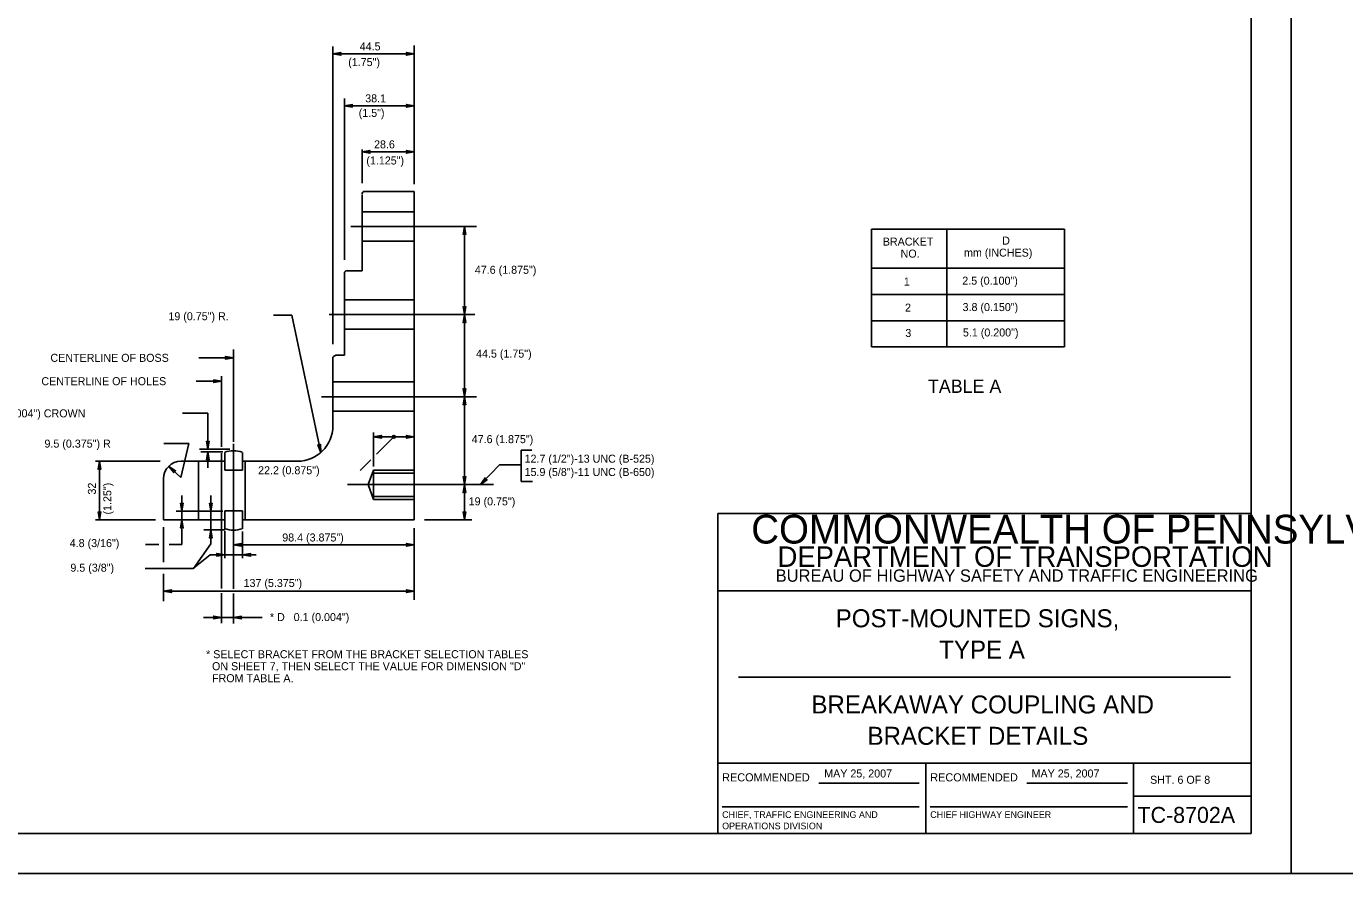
# Model space of a CAD drawing. Extents: x 637580 to 641008, y 294594 to 295782.
# Drawn here: x 638788.2 to 639282.3, y 294593.6 to 294911.2 of the extents above; entities that cross this region are included whole.
import ezdxf

# ---------------------------------------------------------------- set-up
doc = ezdxf.new("R2010")
doc.units = 0
for name, color, linetype in [('1', 7, 'Continuous'), ('2', 7, 'Continuous'), ('3', 7, 'Continuous'), ('PLT-BNDY', 7, 'Continuous')]:
    doc.layers.add(name, color=color, linetype=linetype)

# ---------------------------------------------------------------- blocks, each defined once
blk = doc.blocks.new('RARROW')
at = {"layer": '3'}
blk.add_lwpolyline([(-2.2695, 0.285), (-2.184875, 0.12075), (0, 0), (-2.2695, 0.285), (-2.38575, 0.384625), (0, 0), (-2.183125, -0.108), (-2.262875, -0.2705), (0, 0), (-2.38575, -0.379125), (-2.262875, -0.2705)], dxfattribs=at)

msp = doc.modelspace()

# ---------------------------------------------------------------- linework, layer by layer
at = {"layer": '1'}
for p, q in [((639247.31, 294608.63), (639247.31, 295172.63)), ((639047.31, 294608.63), (639047.31, 294728.63)), ((639047.31, 294728.63), (639247.31, 294728.63)), ((639247.31, 294699.63), (639047.31, 294699.63)), ((639055.06, 294667.31), (639239.56, 294667.31)), ((639047.31, 294635), (639247.31, 294635)), ((639125.31, 294635), (639125.31, 294608.63)), ((639203.19, 294608.63), (639203.19, 294635)), ((639085.24, 294627.57), (639122.87, 294627.57)), ((639163.24, 294627.57), (639200.87, 294627.57)), ((639203.19, 294622.63), (639247.31, 294622.63)), ((639048.99, 294618.68), (639122.87, 294618.68)), ((639126.99, 294618.68), (639200.87, 294618.68)), ((639247.31, 294608.63), (638461.31, 294608.63)), ((638461.31, 294608.63), (639047.31, 294608.63))]:
    msp.add_line(p, q, dxfattribs=at)
at = {"layer": '2'}
for p, q in [((638903.08, 294792.1), (638903.08, 294903.63)), ((638933.59, 294852.04), (638933.59, 294904.07)), ((638933.59, 294900.92), (638903.08, 294900.92)), ((638907.4, 294823.69), (638907.4, 294884.24)), ((638933.59, 294881.47), (638907.4, 294881.47)), ((638914.02, 294852.45), (638914.02, 294865.12)), ((638933.59, 294864.18), (638914.02, 294864.18)), ((638933.59, 294849.34), (638914.96, 294849.34)), ((638933.59, 294836.25), (638933.59, 294849.34)), ((638914.02, 294848.13), (638914.02, 294819.64)), ((638933.59, 294841.65), (638914.02, 294841.65)), ((638909.83, 294836.25), (638933.59, 294836.25)), ((638933.59, 294803.17), (638933.59, 294836.25)), ((638956.95, 294836.25), (638933.59, 294836.25)), ((638952.36, 294803.17), (638952.36, 294836.25)), ((639104.98, 294835.25), (639104.98, 294791.12)), ((639177.33, 294835.25), (639104.98, 294835.25)), ((639133.23, 294835.25), (639133.23, 294791.12)), ((639177.33, 294835.25), (639177.33, 294791.12)), ((638933.59, 294830.71), (638914.02, 294830.71)), ((638914.02, 294819.64), (638908.48, 294819.64)), ((639177.33, 294820.62), (639104.98, 294820.62)), ((638907.4, 294818.7), (638907.4, 294787.92)), ((639177.33, 294810.75), (639104.98, 294810.75)), ((638933.59, 294808.71), (638907.4, 294808.71)), ((638887.67, 294802.93), (638880.76, 294802.93)), ((638887.67, 294802.93), (638898.59, 294751.54)), ((638901.73, 294803.17), (638933.59, 294803.17)), ((638933.59, 294772.39), (638933.59, 294803.17)), ((638956.27, 294803.17), (638933.59, 294803.17)), ((638952.36, 294772.39), (638952.36, 294803.17)), ((639177.33, 294800.87), (639104.98, 294800.87)), ((638933.59, 294797.77), (638907.4, 294797.77)), ((638865.82, 294755.52), (638865.82, 294790.08)), ((639177.33, 294791.12), (639104.98, 294791.12)), ((638865.82, 294786.97), (638852.79, 294786.97)), ((638903.08, 294786.84), (638903.08, 294761.46)), ((638907.4, 294787.92), (638904.03, 294787.92)), ((638861.37, 294753.63), (638861.37, 294780.09)), ((638861.37, 294778.2), (638851.86, 294778.2)), ((638933.59, 294777.93), (638903.08, 294777.93)), ((638898.76, 294772.39), (638933.59, 294772.39)), ((638933.59, 294739.45), (638933.59, 294772.39)), ((638956.95, 294772.39), (638933.59, 294772.39)), ((638952.36, 294739.45), (638952.36, 294772.39)), ((638856.24, 294766.18), (638846.75, 294766.18)), ((638856.24, 294752.68), (638856.24, 294766.18)), ((638933.59, 294766.99), (638903.08, 294766.99)), ((638918.34, 294746.2), (638918.34, 294759.02)), ((638933.59, 294757.4), (638918.34, 294757.4)), ((638925.96, 294757.4), (638919.38, 294750.81)), ((638849.08, 294754.84), (638839.71, 294754.84)), ((638849.08, 294754.84), (638846.11, 294742.15)), ((638864.47, 294752.68), (638853.13, 294752.68)), ((638861.77, 294751.74), (638853.54, 294751.74)), ((638856.24, 294745.8), (638856.24, 294751.74)), ((638861.37, 294721.09), (638861.37, 294751.2)), ((638862.58, 294751.47), (638862.58, 294744.85)), ((638865.82, 294742.83), (638865.82, 294754.71)), ((638869.2, 294744.85), (638869.2, 294751.47)), ((638977.71, 294752.39), (638973.69, 294752.39)), ((638973.69, 294740.63), (638973.69, 294752.39)), ((638838.28, 294748.23), (638814.12, 294748.23)), ((638815.6, 294726.22), (638815.6, 294748.23)), ((638846.11, 294742.15), (638841.54, 294746.3)), ((638846.11, 294748.23), (638862.58, 294748.23)), ((638852.73, 294748.23), (638852.73, 294726.22)), ((638869.2, 294748.23), (638889.85, 294748.23)), ((638870.14, 294726.22), (638870.14, 294748.23)), ((638917.34, 294748.77), (638913.36, 294744.79)), ((638965.59, 294746.88), (638958.43, 294739.45)), ((638973.69, 294746.88), (638965.59, 294746.88)), ((638839.63, 294726.22), (638839.63, 294741.48)), ((638862.58, 294744.85), (638869.2, 294744.85)), ((638865.82, 294744.85), (638865.82, 294744.85)), ((638865.82, 294731.62), (638865.82, 294742.83)), ((638918.34, 294744.85), (638916.31, 294739.45)), ((638933.59, 294744.85), (638918.34, 294744.85)), ((638918.34, 294733.92), (638918.34, 294744.85)), ((638933.59, 294743.77), (638918.34, 294743.77)), ((638977.93, 294740.63), (638973.69, 294740.63)), ((638846.52, 294716.98), (638846.52, 294735.4)), ((638857.32, 294717.31), (638857.32, 294735.4)), ((638861.37, 294735.67), (638861.37, 294735.67)), ((638861.37, 294735.67), (638861.37, 294735.67)), ((638908.62, 294739.45), (638933.59, 294739.45)), ((638916.31, 294739.45), (638918.34, 294733.92)), ((638933.59, 294726.22), (638933.59, 294739.45)), ((638963.29, 294739.45), (638933.59, 294739.45)), ((638952.36, 294726.22), (638952.36, 294739.45)), ((638865.82, 294720.69), (638865.82, 294731.62)), ((638933.59, 294735), (638918.34, 294735)), ((638933.59, 294733.92), (638918.34, 294733.92)), ((638836.53, 294726.22), (638814.12, 294726.22)), ((638839.63, 294726.22), (638839.63, 294726.22)), ((638839.63, 294726.22), (638862.58, 294726.22)), ((638861.77, 294729.46), (638844.36, 294729.46)), ((638862.58, 294729.6), (638869.2, 294729.6)), ((638862.58, 294722.85), (638862.58, 294729.6)), ((638865.82, 294729.6), (638865.82, 294729.6)), ((638869.2, 294729.6), (638869.2, 294722.85)), ((638869.2, 294726.22), (638933.59, 294726.22)), ((638955.19, 294726.22), (638937.37, 294726.22)), ((638839.63, 294710.43), (638839.63, 294723.52)), ((638862.72, 294722.44), (638854.75, 294722.44)), ((638861.37, 294700.45), (638861.37, 294721.09)), ((638862.58, 294711.91), (638862.58, 294722.04)), ((638865.82, 294700.33), (638865.82, 294720.69)), ((638869.2, 294711.91), (638869.2, 294721.9)), ((638933.59, 294696.25), (638933.59, 294723.12)), ((638837.79, 294716.98), (638832.85, 294716.98)), ((638846.52, 294716.98), (638841.72, 294716.98)), ((638857.32, 294717.31), (638850.84, 294708)), ((638933.59, 294716.91), (638865.82, 294716.91)), ((638857.05, 294713.13), (638850.84, 294708.13)), ((638874.33, 294713.13), (638857.05, 294713.13)), ((638850.84, 294708), (638832.7, 294708)), ((638839.63, 294695.71), (638839.63, 294705.97)), ((638933.59, 294699.49), (638839.63, 294699.49)), ((638861.37, 294687.48), (638861.37, 294698.71)), ((638865.82, 294687.34), (638865.82, 294698.65)), ((638876.57, 294689.64), (638854.62, 294689.64))]:
    msp.add_line(p, q, dxfattribs=at)
msp.add_circle((638925.96, 294757.4), 0.5, dxfattribs=at)
msp.add_arc((638889.85, 294761.46), 13.23, 270, 0, dxfattribs=at)
for centre, major_axis, ratio, start_param, end_param in [((638915.09, 294848.27), (0, -1.1), 0.996388, 3.141593, 4.712389), ((638908.5, 294818.61), (0, -1.1), 0.996388, 3.141593, 4.712389), ((638904.12, 294786.75), (0, -1.1), 0.996388, 3.141593, 4.712389), ((638865.84, 294741.81), (0, -10.3), 0.996388, 2.814747, 3.468439), ((638846.14, 294741.63), (0, -6.6), 0.985297, 3.141593, 4.712389), ((638865.84, 294732.68), (0, -10.3), 0.996388, 5.956339, 6.610031)]:
    msp.add_ellipse(centre, major_axis=major_axis, ratio=ratio, start_param=start_param, end_param=end_param, dxfattribs=at)
at = {"layer": 'PLT-BNDY'}
for points in [[(638421.31, 295187.63), (639262.31, 295187.63), (639262.31, 294593.63), (638421.31, 294593.63)], [(639262.31, 295187.63), (640103.31, 295187.63), (640103.31, 294593.63), (639262.31, 294593.63)]]:
    msp.add_lwpolyline(points, close=True, dxfattribs=at)

# ---------------------------------------------------------------- block references
at = {"layer": '2'}
for p, xscale, yscale, rotation in [((638903.08, 294900.91), 1.2574347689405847, 1.3092961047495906, 180), ((638907.4, 294881.47), 1.2574347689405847, 1.3092961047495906, 180), ((638914.02, 294864.18), 1.2574347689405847, 1.3092961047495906, 180), ((638952.36, 294836.25), 1.2574347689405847, 1.3092961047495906, 89.99999999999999), ((638952.36, 294803.17), 1.2574347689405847, 1.3092961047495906, -90.00000000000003), ((638952.36, 294803.17), 1.2574347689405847, 1.3092961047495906, 89.99999999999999), ((638952.36, 294772.39), 1.2574347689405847, 1.3092961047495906, -90.00000000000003), ((638952.36, 294772.39), 1.2574347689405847, 1.3092961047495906, 89.99999999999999), ((638856.24, 294752.68), 1.2574347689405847, 1.3092961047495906, -90.00000000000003), ((638918.34, 294757.4), 1.2574347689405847, 1.3092961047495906, 180), ((638856.24, 294751.74), 1.2574347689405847, 1.3092961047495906, 89.99999999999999), ((638898.59, 294751.54), 1.257434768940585, 1.3092961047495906, -78.10678837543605), ((638815.6, 294748.23), 1.2574347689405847, 1.3092961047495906, 89.99999999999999), ((638841.54, 294746.3), 1.2574347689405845, 1.3092961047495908, 138.25928815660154), ((638952.36, 294739.45), 1.2574347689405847, 1.3092961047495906, -90.00000000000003), ((638958.43, 294739.45), 1.2574347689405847, 1.3092961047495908, -133.92986856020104), ((638952.36, 294739.45), 1.2574347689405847, 1.3092961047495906, 89.99999999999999), ((638846.52, 294729.46), 1.2574347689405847, 1.3092961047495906, -90.00000000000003), ((638857.32, 294729.46), 1.2574347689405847, 1.3092961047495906, -90.00000000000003), ((638815.6, 294726.22), 1.2574347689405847, 1.3092961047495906, -90.00000000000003), ((638846.52, 294726.22), 1.2574347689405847, 1.3092961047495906, 89.99999999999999), ((638952.36, 294726.22), 1.2574347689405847, 1.3092961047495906, -90.00000000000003), ((638857.32, 294722.44), 1.2574347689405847, 1.3092961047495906, 89.99999999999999), ((638865.82, 294716.91), 1.2574347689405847, 1.3092961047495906, 180), ((638869.2, 294713.13), 1.2574347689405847, 1.3092961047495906, 180), ((638839.63, 294699.49), 1.2574347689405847, 1.3092961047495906, 180), ((638865.82, 294689.64), 1.2574347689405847, 1.3092961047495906, 180)]:
    msp.add_blockref('RARROW', p, dxfattribs=dict(at, xscale=xscale, yscale=yscale, rotation=rotation))
at = {"layer": '2', "xscale": 1.2574347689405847, "yscale": 1.3092961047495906}
for p in [(638933.59, 294900.91), (638933.59, 294881.47), (638933.59, 294864.18), (638865.82, 294786.97), (638861.37, 294778.2), (638933.59, 294757.4), (638933.59, 294716.91), (638862.58, 294713.13), (638933.59, 294699.49), (638861.37, 294689.64)]:
    msp.add_blockref('RARROW', p, dxfattribs=at)

# ---------------------------------------------------------------- texts
at = {"layer": '1'}
for s, height, p in [('COMMONWEALTH OF PENNSYLVANIA', 10.7828, (639059.9, 294717.36)), ('DEPARTMENT OF TRANSPORTATION', 7.6837, (639069.76, 294708.61)), ('BUREAU OF HIGHWAY SAFETY AND TRAFFIC ENGINEERING', 4.6253, (639069.04, 294703.04)), ('POST-MOUNTED SIGNS,', 6.75, (639091.54, 294685.97)), ('TYPE A', 6.75, (639130.35, 294674.22)), ('BREAKAWAY COUPLING AND', 6.75, (639082.45, 294653.66)), ('BRACKET DETAILS', 6.75, (639103.47, 294641.91)), ('RECOMMENDED', 3.048, (639048.99, 294628.2)), ('RECOMMENDED', 3.048, (639126.99, 294628.2)), ('SHT. 6 OF 8', 3, (639209.4, 294627.31)), ('CHIEF, TRAFFIC ENGINEERING AND', 2.5, (639048.99, 294614.51)), ('CHIEF HIGHWAY ENGINEER', 2.5, (639126.99, 294614.51)), ('TC-8702A', 6, (639204.68, 294612.63)), ('OPERATIONS DIVISION', 2.5, (639048.99, 294610.26))]:
    msp.add_text(s, height=height, dxfattribs=at).set_placement(p)
at = {"layer": '2'}
for s, height, p in [('TABLE A', 5, (639126.13, 294773.83)), ('MAY 25, 2007', 3, (639087.25, 294629.67)), ('MAY 25, 2007', 3, (639164.97, 294629.67))]:
    msp.add_text(s, height=height, dxfattribs=at).set_placement(p)
at = {"layer": '3'}
for s, p in [('44.5', (638913.13, 294902.21)), ('(1.75")', (638908.83, 294896.34)), ('38.1', (638915.2, 294882.73)), ('(1.5") ', (638912.76, 294877.28)), ('28.6 ', (638918.5, 294865.49)), ('(1.125") ', (638915.62, 294859.45)), ('BRACKET', (639109.2, 294829.04)), ('D', (639153.94, 294829.41)), ('NO.', (639115.88, 294824.54)), ('mm (INCHES)', (639139.64, 294824.91)), ('47.6 (1.875")', (638956.29, 294818.47)), ('1', (639117.08, 294814.08)), ('2.5 (0.100")', (639138.99, 294814.39)), ('2', (639117.53, 294804.29)), ('3.8 (0.150")', (639139.11, 294804.5)), ('19 (0.75") R.', (638841.43, 294801.06)), ('3', (639117.65, 294794.79)), ('5.1 (0.200")', (639139.24, 294794.98)), ('44.5 (1.75")', (638956.75, 294787.05)), ('CENTERLINE OF BOSS', (638797.21, 294785.47)), ('CENTERLINE OF HOLES', (638793.81, 294776.72)), ('0.76 (0.03")  0.1 (0.004") CROWN', (638749.72, 294764.66)), (' 9.5 (0.375") R', (638793.86, 294753.32)), ('47.6 (1.875")', (638955.12, 294754.99)), ('12.7 (1/2")-13 UNC (B-525)', (638974.93, 294747.67)), ('22.2 (0.875")', (638875.05, 294743.33)), ('15.9 (5/8")-11 UNC (B-650)', (638974.93, 294742.67)), ('19 (0.75")', (638953.97, 294731.67)), ('98.4 (3.875")', (638884.1, 294718.13)), (' 4.8 (3/16")', (638803.33, 294716.03)), (' 9.5 (3/8")', (638803.58, 294706.81)), ('137 (5.375")', (638869.6, 294701.08)), ('* D   0.1 (0.004")', (638879.47, 294688.3)), ('  * SELECT BRACKET FROM THE BRACKET SELECTION TABLES', (638853.32, 294674.38)), ('    ON SHEET 7, THEN SELECT THE VALUE FOR DIMENSION "D"', (638853.32, 294669.88)), ('    FROM TABLE A.', (638853.32, 294665.38))]:
    msp.add_text(s, height=3, dxfattribs=at).set_placement(p)
for s, p in [('32 ', (638814.25, 294735.72)), ('(1.25")', (638820.04, 294728.24))]:
    msp.add_text(s, height=3, rotation=90, dxfattribs=at).set_placement(p)

doc.saveas('drawing.dxf')
